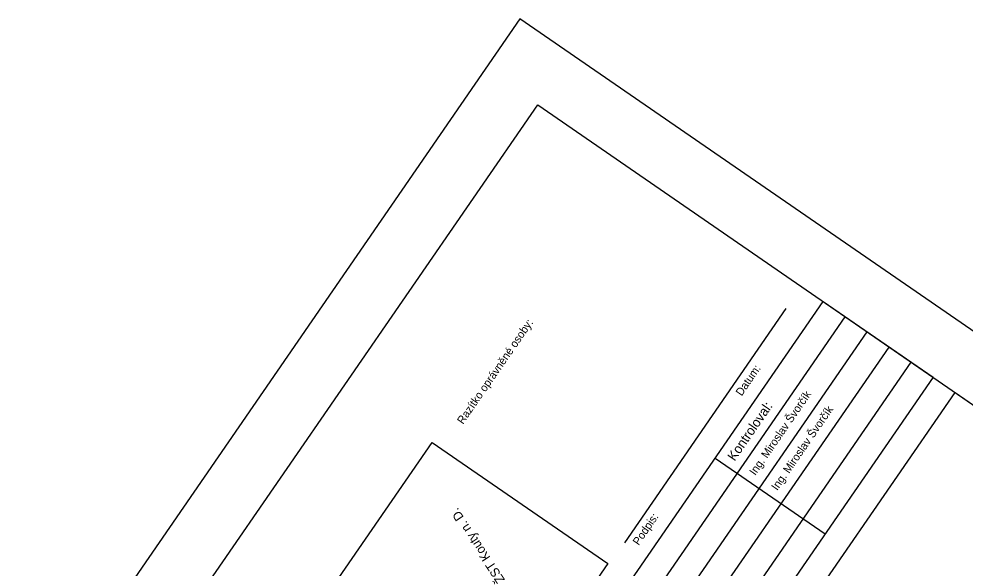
# Model space of a CAD drawing. Extents: x -558199 to -558019, y -1073463 to -1073248.
# Drawn here: x -558104.84 to -558058.28, y -1073274.56 to -1073247.54 of the extents above; entities that cross this region are included whole.
import ezdxf

# ---------------------------------------------------------------- set-up
doc = ezdxf.new("R2010")
doc.units = 0
for name, color, linetype in [('Rozpiska_pola_3', 7, 'Continuous'), ('Rozpiska_pole_1', 7, 'Continuous'), ('Rozpiska_pole_2', 7, 'Continuous'), ('Rozpiska_pole_4', 7, 'Continuous'), ('Rozpiska_pole_5', 7, 'Continuous'), ('Rozpiska_pole_7', 7, 'Continuous'), ('Rámeček', 7, 'Continuous')]:
    doc.layers.add(name, color=color, linetype=linetype)

# ---------------------------------------------------------------- blocks, each defined once
blk = doc.blocks.new('_U3')
at = {"layer": 'Rozpiska_pola_3'}
blk.add_line((-26.675, -18.2505), (26.675, -18.2505), dxfattribs=at)
for s, p in [('Razítko oprávněné osoby:', (-25.675, 19.2495)), ('Podpis:', (-25.675, -20.7505)), ('Datum:', (8.325, -20.7505))]:
    blk.add_text(s, height=1.5, dxfattribs=at).set_placement(p)
blk = doc.blocks.new('_U7')
at = {"layer": 'Rozpiska_pole_2'}
blk.add_lwpolyline([(-53.3255, 20.0005), (53.3245, 20.0005), (53.3245, -19.9995), (-53.3255, -19.9995)], close=True, dxfattribs=at)
blk.add_text('Orientační schéma:', height=1.5, dxfattribs=at).set_placement((-47.6755, 17.5005))

msp = doc.modelspace()

# ---------------------------------------------------------------- linework, layer by layer
at = {"layer": 'Rozpiska_pole_1'}
msp.add_lwpolyline([(-558104.635, -1073288.508), (-558079.308, -1073251.767), (-558023.115, -1073290.501), (-558048.441, -1073327.243)], close=True, dxfattribs=at)
at = {"layer": 'Rozpiska_pole_4'}
for p, q in [((-558089.506, -1073298.937), (-558064.179, -1073262.195)), ((-558088.425, -1073299.682), (-558063.099, -1073262.94)), ((-558087.344, -1073300.427), (-558062.018, -1073263.685)), ((-558086.264, -1073301.172), (-558060.937, -1073264.43)), ((-558065.175, -1073272.89), (-558070.579, -1073269.166))]:
    msp.add_line(p, q, dxfattribs=at)
msp.add_lwpolyline([(-558090.586, -1073298.192), (-558065.26, -1073261.45), (-558059.857, -1073265.175), (-558085.183, -1073301.917)], close=True, dxfattribs=at)
at = {"layer": 'Rozpiska_pole_5'}
msp.add_lwpolyline([(-558084.103, -1073302.661), (-558058.776, -1073265.92), (-558053.373, -1073269.644), (-558078.699, -1073306.386)], close=True, dxfattribs=at)
at = {"layer": 'Rámeček'}
msp.add_lwpolyline([(-558019.047, -1073289.661), (-558080.194, -1073247.54), (-558199.323, -1073420.48), (-558138.176, -1073462.601)], close=True, dxfattribs=at)

# ---------------------------------------------------------------- block references
at = {"layer": 'Rozpiska_pola_3', "xscale": 0.2625000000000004, "yscale": 0.26250000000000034, "rotation": 55.42136593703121}
msp.add_blockref('_U3', (-558075.004, -1073264.832), dxfattribs=at)
at = {"layer": 'Rozpiska_pole_2', "xscale": 0.2625000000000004, "yscale": 0.26250000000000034, "rotation": 55.42136593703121}
msp.add_blockref('_U7', (-558088.129, -1073282.885), dxfattribs=at)

# ---------------------------------------------------------------- texts
at = {"layer": 'Rozpiska_pole_4'}
for s, height, p in [('Ing. Miroslav Švorčík', 0.39375, (-558068.609, -1073270.031)), ('Kontroloval:', 0.4725, (-558069.625, -1073269.33)), ('Ing. Miroslav Švorčík', 0.39375, (-558067.528, -1073270.775))]:
    msp.add_text(s, height=height, rotation=55.4214, dxfattribs=at).set_placement(p)
at = {"layer": 'Rozpiska_pole_7'}
msp.add_text('ŽST Kouty n. D.', height=0.45, rotation=123.3122, dxfattribs=at).set_placement((-558080.914, -1073275.133))

doc.saveas('drawing.dxf')
